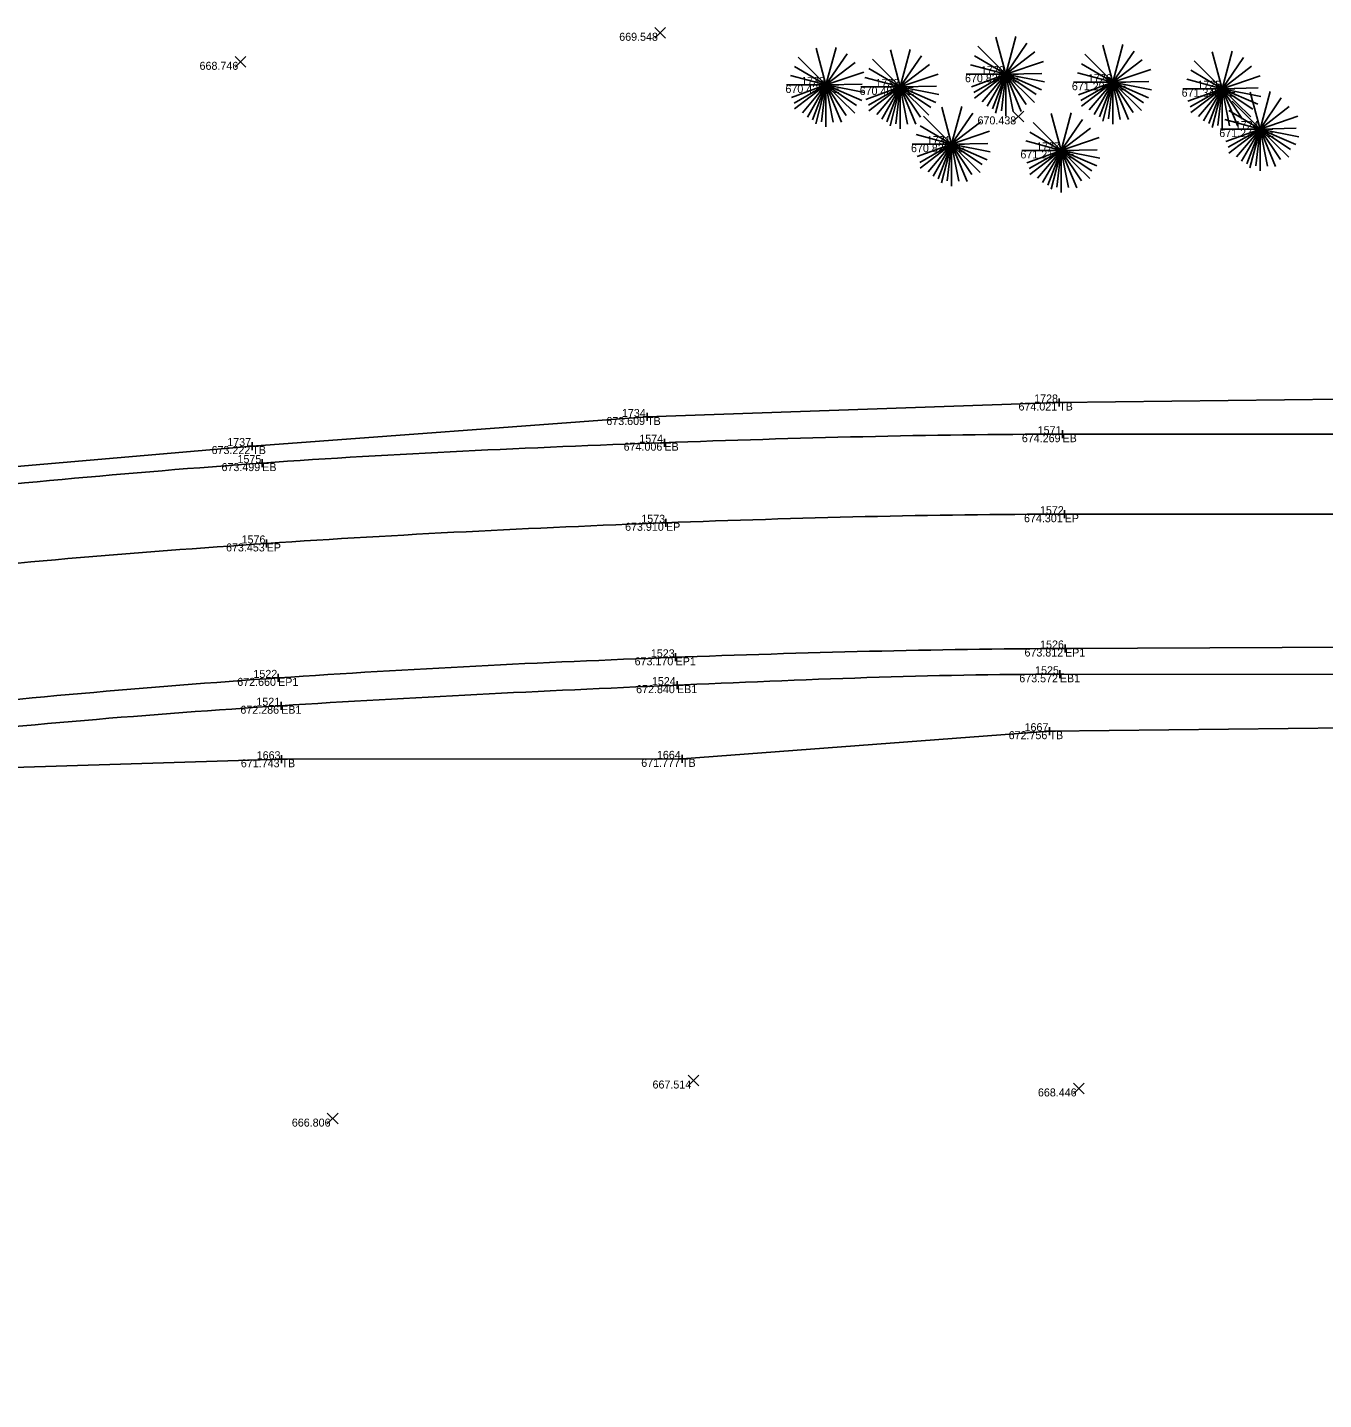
# Model space of a CAD drawing. Extents: x 2197382 to 2204062, y 634117 to 636522.
# Drawn here: x 2203379.7 to 2203541.7, y 635413 to 635584.5 of the extents above; entities that cross this region are included whole.
import ezdxf

# ---------------------------------------------------------------- set-up
doc = ezdxf.new("R2010")
doc.units = 0
for name, color, linetype in [('_CIVIL_CONSTRUCTION', 7, 'Continuous'), ('GE_P_Alignment_100_Bearings', 7, 'Continuous'), ('GE_P_Alignment_100_Distances', 7, 'Continuous'), ('GE_X_Alignment', 7, 'Continuous'), ('PF_P_Grade_Line', 7, 'Continuous'), ('RW_X_CL_100_Curve_Data', 7, 'Continuous'), ('SH_Border', 7, 'Continuous'), ('SH_Cut_Line', 7, 'Continuous'), ('SH_Data', 7, 'Continuous')]:
    doc.layers.add(name, color=color, linetype=linetype)

msp = doc.modelspace()

# ---------------------------------------------------------------- linework, layer by layer
at = {"layer": '_CIVIL_CONSTRUCTION'}
for p, q in [((2203508.13, 635537.6), (2203509.13, 635537.6)), ((2203508.63, 635538.1), (2203508.63, 635537.1)), ((2203508.63, 635537.6), (2203508.63, 635537.6)), ((2203456.64, 635535.79), (2203457.64, 635535.79)), ((2203457.14, 635536.29), (2203457.14, 635535.29)), ((2203457.14, 635535.79), (2203457.14, 635535.79)), ((2203508.55, 635533.64), (2203509.55, 635533.64)), ((2203509.05, 635534.14), (2203509.05, 635533.14)), ((2203509.05, 635533.64), (2203509.05, 635533.64)), ((2203407.3, 635532.16), (2203408.3, 635532.16)), ((2203407.8, 635532.66), (2203407.8, 635531.66)), ((2203407.8, 635532.16), (2203407.8, 635532.16)), ((2203458.81, 635532.58), (2203459.81, 635532.58)), ((2203459.31, 635533.08), (2203459.31, 635532.08)), ((2203459.31, 635532.58), (2203459.31, 635532.58)), ((2203408.55, 635530.03), (2203409.55, 635530.03)), ((2203409.05, 635530.53), (2203409.05, 635529.53)), ((2203409.05, 635530.03), (2203409.05, 635530.03)), ((2203459.5, 635523.07), (2203459.5, 635522.07)), ((2203508.82, 635523.64), (2203509.82, 635523.64)), ((2203509.32, 635524.14), (2203509.32, 635523.14)), ((2203509.32, 635523.64), (2203509.32, 635523.64)), ((2203459, 635522.57), (2203460, 635522.57)), ((2203459.5, 635522.57), (2203459.5, 635522.57)), ((2203409.1, 635519.99), (2203410.1, 635519.99)), ((2203409.6, 635520.49), (2203409.6, 635519.49)), ((2203409.6, 635519.99), (2203409.6, 635519.99)), ((2203460.7, 635506.26), (2203460.7, 635505.26)), ((2203508.87, 635506.86), (2203509.87, 635506.86)), ((2203509.37, 635507.36), (2203509.37, 635506.36)), ((2203509.37, 635506.86), (2203509.37, 635506.86)), ((2203460.2, 635505.76), (2203461.2, 635505.76)), ((2203460.7, 635505.76), (2203460.7, 635505.76)), ((2203508.72, 635504.14), (2203508.72, 635503.14)), ((2203410.54, 635503.19), (2203411.54, 635503.19)), ((2203411.04, 635503.69), (2203411.04, 635502.69)), ((2203411.04, 635503.19), (2203411.04, 635503.19)), ((2203460.88, 635502.78), (2203460.88, 635501.78)), ((2203508.22, 635503.64), (2203509.22, 635503.64)), ((2203508.72, 635503.64), (2203508.72, 635503.64)), ((2203460.38, 635502.28), (2203461.38, 635502.28)), ((2203460.88, 635502.28), (2203460.88, 635502.28)), ((2203410.92, 635499.71), (2203411.92, 635499.71)), ((2203411.42, 635500.21), (2203411.42, 635499.21)), ((2203411.42, 635499.71), (2203411.42, 635499.71)), ((2203506.92, 635496.53), (2203507.92, 635496.53)), ((2203507.42, 635497.03), (2203507.42, 635496.03)), ((2203507.42, 635496.53), (2203507.42, 635496.53)), ((2203410.95, 635493.02), (2203411.95, 635493.02)), ((2203411.45, 635493.52), (2203411.45, 635492.52)), ((2203411.45, 635493.02), (2203411.45, 635493.02)), ((2203461.01, 635493.07), (2203462.01, 635493.07)), ((2203461.51, 635493.57), (2203461.51, 635492.57)), ((2203461.51, 635493.07), (2203461.51, 635493.07))]:
    msp.add_line(p, q, dxfattribs=at)
at = {"layer": 'GE_P_Alignment_100_Bearings'}
for p, q in [((2203501.95, 635578.62), (2203500.72, 635583.23)), ((2203501.95, 635578.62), (2203503.21, 635583.32)), ((2203479.49, 635577.28), (2203478.25, 635581.89)), ((2203479.49, 635577.28), (2203480.75, 635581.97)), ((2203488.78, 635577.03), (2203487.54, 635581.65)), ((2203488.78, 635577.03), (2203490.03, 635581.73)), ((2203501.95, 635578.62), (2203498.46, 635582.11)), ((2203501.95, 635578.62), (2203504.61, 635582.51)), ((2203501.95, 635578.62), (2203505.61, 635581.43)), ((2203515.34, 635577.62), (2203514.11, 635582.23)), ((2203515.34, 635577.62), (2203516.6, 635582.32)), ((2203515.34, 635577.62), (2203518, 635581.51)), ((2203529, 635576.81), (2203527.77, 635581.42)), ((2203529, 635576.81), (2203530.26, 635581.51)), ((2203479.49, 635577.28), (2203475.58, 635579.57)), ((2203479.49, 635577.28), (2203476, 635580.76)), ((2203479.49, 635577.28), (2203482.15, 635581.16)), ((2203479.49, 635577.28), (2203483.15, 635580.08)), ((2203488.78, 635577.03), (2203485.29, 635580.52)), ((2203488.78, 635577.03), (2203491.43, 635580.92)), ((2203488.78, 635577.03), (2203492.43, 635579.84)), ((2203501.95, 635578.62), (2203497.54, 635579.8)), ((2203501.95, 635578.62), (2203498.05, 635580.92)), ((2203501.95, 635578.62), (2203506.69, 635580.23)), ((2203515.34, 635577.62), (2203511.44, 635579.92)), ((2203515.34, 635577.62), (2203511.85, 635581.11)), ((2203515.34, 635577.62), (2203519, 635580.42)), ((2203529, 635576.81), (2203525.51, 635580.3)), ((2203529, 635576.81), (2203531.66, 635580.7)), ((2203529, 635576.81), (2203532.66, 635579.62)), ((2203479.49, 635577.28), (2203475.08, 635578.46)), ((2203479.49, 635577.28), (2203484.23, 635578.88)), ((2203488.78, 635577.03), (2203484.36, 635578.22)), ((2203488.78, 635577.03), (2203484.87, 635579.33)), ((2203488.78, 635577.03), (2203493.51, 635578.64)), ((2203497.02, 635578.62), (2203501.95, 635578.62)), ((2203501.95, 635578.62), (2203497.66, 635577.06)), ((2203501.95, 635578.62), (2203497.97, 635576.34)), ((2203501.95, 635578.62), (2203498.05, 635575.63)), ((2203501.95, 635578.62), (2203499.01, 635575.15)), ((2203501.95, 635578.62), (2203499.63, 635574.61)), ((2203501.95, 635578.62), (2203500.29, 635574.28)), ((2203501.95, 635578.62), (2203500.69, 635573.76)), ((2203501.95, 635578.62), (2203501.41, 635574.03)), ((2203501.95, 635578.62), (2203506.46, 635578.71)), ((2203501.95, 635573.38), (2203501.95, 635578.62)), ((2203501.95, 635578.62), (2203502.87, 635573.98)), ((2203501.95, 635578.62), (2203503.89, 635573.95)), ((2203501.95, 635578.62), (2203504.49, 635574.83)), ((2203501.95, 635578.62), (2203505.54, 635575.1)), ((2203501.95, 635578.62), (2203505.77, 635576.07)), ((2203501.95, 635578.62), (2203506.42, 635576.68)), ((2203501.95, 635578.62), (2203506.78, 635577.66)), ((2203515.34, 635577.62), (2203510.93, 635578.8)), ((2203515.34, 635577.62), (2203520.08, 635579.23)), ((2203529, 635576.81), (2203524.59, 635577.99)), ((2203529, 635576.81), (2203525.1, 635579.11)), ((2203529, 635576.81), (2203533.74, 635578.42)), ((2203474.55, 635577.28), (2203479.49, 635577.28)), ((2203479.49, 635577.28), (2203475.2, 635575.71)), ((2203479.49, 635577.28), (2203475.51, 635574.99)), ((2203479.49, 635577.28), (2203475.58, 635574.28)), ((2203479.49, 635577.28), (2203476.54, 635573.81)), ((2203479.49, 635577.28), (2203477.17, 635573.26)), ((2203479.49, 635577.28), (2203477.82, 635572.94)), ((2203479.49, 635577.28), (2203478.23, 635572.42)), ((2203479.49, 635577.28), (2203478.95, 635572.68)), ((2203479.49, 635577.28), (2203484, 635577.37)), ((2203479.49, 635572.04), (2203479.49, 635577.28)), ((2203479.49, 635577.28), (2203480.41, 635572.64)), ((2203479.49, 635577.28), (2203481.42, 635572.61)), ((2203479.49, 635577.28), (2203482.03, 635573.48)), ((2203479.49, 635577.28), (2203483.08, 635573.75)), ((2203479.49, 635577.28), (2203483.31, 635574.72)), ((2203479.49, 635577.28), (2203483.96, 635575.33)), ((2203479.49, 635577.28), (2203484.32, 635576.32)), ((2203483.84, 635577.03), (2203488.78, 635577.03)), ((2203488.78, 635577.03), (2203484.49, 635575.47)), ((2203488.78, 635577.03), (2203484.79, 635574.75)), ((2203488.78, 635577.03), (2203484.87, 635574.04)), ((2203488.78, 635577.03), (2203485.83, 635573.57)), ((2203488.78, 635577.03), (2203486.46, 635573.02)), ((2203488.78, 635577.03), (2203487.11, 635572.69)), ((2203488.78, 635577.03), (2203487.51, 635572.18)), ((2203488.78, 635577.03), (2203488.23, 635572.44)), ((2203488.78, 635577.03), (2203493.29, 635577.12)), ((2203488.78, 635571.79), (2203488.78, 635577.03)), ((2203488.78, 635577.03), (2203489.7, 635572.4)), ((2203488.78, 635577.03), (2203490.71, 635572.36)), ((2203488.78, 635577.03), (2203491.31, 635573.24)), ((2203488.78, 635577.03), (2203492.36, 635573.51)), ((2203488.78, 635577.03), (2203492.6, 635574.48)), ((2203488.78, 635577.03), (2203493.24, 635575.09)), ((2203488.78, 635577.03), (2203493.6, 635576.07)), ((2203510.41, 635577.62), (2203515.34, 635577.62)), ((2203515.34, 635577.62), (2203511.05, 635576.06)), ((2203515.34, 635577.62), (2203511.36, 635575.34)), ((2203515.34, 635577.62), (2203511.44, 635574.62)), ((2203515.34, 635577.62), (2203512.4, 635574.15)), ((2203515.34, 635577.62), (2203513.02, 635573.6)), ((2203515.34, 635577.62), (2203513.68, 635573.28)), ((2203515.34, 635577.62), (2203514.08, 635572.76)), ((2203515.34, 635577.62), (2203514.8, 635573.03)), ((2203515.34, 635577.62), (2203519.85, 635577.71)), ((2203515.34, 635572.38), (2203515.34, 635577.62)), ((2203515.34, 635577.62), (2203516.26, 635572.98)), ((2203515.34, 635577.62), (2203517.28, 635572.95)), ((2203515.34, 635577.62), (2203517.88, 635573.83)), ((2203515.34, 635577.62), (2203518.93, 635574.1)), ((2203515.34, 635577.62), (2203519.16, 635575.06)), ((2203515.34, 635577.62), (2203519.81, 635575.68)), ((2203515.34, 635577.62), (2203520.17, 635576.66)), ((2203524.07, 635576.81), (2203529, 635576.81)), ((2203529, 635576.81), (2203524.71, 635575.25)), ((2203529, 635576.81), (2203525.02, 635574.53)), ((2203529, 635576.81), (2203525.1, 635573.82)), ((2203529, 635576.81), (2203526.06, 635573.34)), ((2203529, 635576.81), (2203526.68, 635572.8)), ((2203529, 635576.81), (2203527.34, 635572.47)), ((2203529, 635576.81), (2203527.74, 635571.95)), ((2203529, 635576.81), (2203528.46, 635572.22)), ((2203529, 635576.81), (2203533.51, 635576.9)), ((2203529, 635571.57), (2203529, 635576.81)), ((2203529, 635576.81), (2203529.92, 635572.17)), ((2203529, 635576.81), (2203530.94, 635572.14)), ((2203529, 635576.81), (2203531.54, 635573.02)), ((2203529, 635576.81), (2203532.59, 635573.29)), ((2203529, 635576.81), (2203532.82, 635574.26)), ((2203529, 635576.81), (2203533.47, 635574.87)), ((2203529, 635576.81), (2203533.83, 635575.85)), ((2203533.73, 635571.77), (2203532.5, 635576.38)), ((2203533.73, 635571.77), (2203534.99, 635576.47)), ((2203495.19, 635569.88), (2203493.96, 635574.5)), ((2203495.19, 635569.88), (2203496.45, 635574.58)), ((2203533.73, 635571.77), (2203530.25, 635575.26)), ((2203533.73, 635571.77), (2203536.39, 635575.65)), ((2203533.73, 635571.77), (2203537.39, 635574.57)), ((2203495.19, 635569.88), (2203491.7, 635573.37)), ((2203495.19, 635569.88), (2203497.84, 635573.77)), ((2203508.88, 635569.1), (2203507.65, 635573.71)), ((2203508.88, 635569.1), (2203510.14, 635573.8)), ((2203508.88, 635569.1), (2203511.54, 635572.98)), ((2203533.73, 635571.77), (2203529.32, 635572.95)), ((2203533.73, 635571.77), (2203529.83, 635574.07)), ((2203533.73, 635571.77), (2203538.47, 635573.38)), ((2203495.19, 635569.88), (2203490.78, 635571.07)), ((2203495.19, 635569.88), (2203491.28, 635572.18)), ((2203495.19, 635569.88), (2203498.85, 635572.69)), ((2203495.19, 635569.88), (2203499.93, 635571.49)), ((2203508.88, 635569.1), (2203504.98, 635571.39)), ((2203508.88, 635569.1), (2203505.39, 635572.58)), ((2203508.88, 635569.1), (2203512.54, 635571.9)), ((2203528.8, 635571.77), (2203533.73, 635571.77)), ((2203533.73, 635571.77), (2203529.44, 635570.21)), ((2203533.73, 635571.77), (2203529.75, 635569.49)), ((2203533.73, 635571.77), (2203529.83, 635568.77)), ((2203533.73, 635571.77), (2203530.79, 635568.3)), ((2203533.73, 635571.77), (2203531.42, 635567.75)), ((2203533.73, 635571.77), (2203532.07, 635567.43)), ((2203533.73, 635571.77), (2203532.47, 635566.91)), ((2203533.73, 635571.77), (2203533.19, 635567.18)), ((2203533.73, 635571.77), (2203538.25, 635571.86)), ((2203533.73, 635566.53), (2203533.73, 635571.77)), ((2203533.73, 635571.77), (2203534.66, 635567.13)), ((2203533.73, 635571.77), (2203535.67, 635567.1)), ((2203533.73, 635571.77), (2203536.27, 635567.98)), ((2203533.73, 635571.77), (2203537.32, 635568.25)), ((2203533.73, 635571.77), (2203537.56, 635569.21)), ((2203533.73, 635571.77), (2203538.2, 635569.83)), ((2203533.73, 635571.77), (2203538.56, 635570.81)), ((2203490.25, 635569.88), (2203495.19, 635569.88)), ((2203495.19, 635569.88), (2203490.9, 635568.32)), ((2203495.19, 635569.88), (2203491.21, 635567.6)), ((2203495.19, 635569.88), (2203491.28, 635566.89)), ((2203495.19, 635569.88), (2203492.25, 635566.42)), ((2203495.19, 635569.88), (2203492.87, 635565.87)), ((2203495.19, 635569.88), (2203493.52, 635565.54)), ((2203495.19, 635569.88), (2203493.93, 635565.03)), ((2203495.19, 635569.88), (2203494.65, 635565.29)), ((2203495.19, 635569.88), (2203499.7, 635569.98)), ((2203495.19, 635564.64), (2203495.19, 635569.88)), ((2203495.19, 635569.88), (2203496.11, 635565.25)), ((2203495.19, 635569.88), (2203497.12, 635565.22)), ((2203495.19, 635569.88), (2203497.73, 635566.09)), ((2203495.19, 635569.88), (2203498.78, 635566.36)), ((2203495.19, 635569.88), (2203499.01, 635567.33)), ((2203495.19, 635569.88), (2203499.65, 635567.94)), ((2203495.19, 635569.88), (2203500.02, 635568.93)), ((2203508.88, 635569.1), (2203504.47, 635570.28)), ((2203508.88, 635569.1), (2203513.62, 635570.7)), ((2203503.95, 635569.1), (2203508.88, 635569.1)), ((2203508.88, 635569.1), (2203504.59, 635567.54)), ((2203508.88, 635569.1), (2203504.9, 635566.82)), ((2203508.88, 635569.1), (2203504.98, 635566.1)), ((2203508.88, 635569.1), (2203505.94, 635565.63)), ((2203508.88, 635569.1), (2203506.56, 635565.08)), ((2203508.88, 635569.1), (2203507.22, 635564.76)), ((2203508.88, 635569.1), (2203507.62, 635564.24)), ((2203508.88, 635569.1), (2203508.34, 635564.51)), ((2203508.88, 635569.1), (2203513.39, 635569.19)), ((2203508.88, 635563.86), (2203508.88, 635569.1)), ((2203508.88, 635569.1), (2203509.8, 635564.46)), ((2203508.88, 635569.1), (2203510.82, 635564.43)), ((2203508.88, 635569.1), (2203511.42, 635565.3)), ((2203508.88, 635569.1), (2203512.47, 635565.58)), ((2203508.88, 635569.1), (2203512.7, 635566.54)), ((2203508.88, 635569.1), (2203513.35, 635567.16)), ((2203508.88, 635569.1), (2203513.71, 635568.14))]:
    msp.add_line(p, q, dxfattribs=at)
at = {"layer": 'GE_P_Alignment_100_Distances'}
for p, q in [((2203559.07, 635523.65), (2203509.32, 635523.64)), ((2203509.37, 635506.86), (2203559.68, 635507.08))]:
    msp.add_line(p, q, dxfattribs=at)
for points in [[(2203509.32, 635523.64), (2203492.71, 635523.63), (2203459.45, 635522.77), (2203409.62, 635520.27), (2203359.91, 635516.08), (2203310.49, 635509.4), (2203261.11, 635501.99), (2203212.05, 635492.43), (2203163.49, 635480.65), (2203115.29, 635467.72), (2203067.64, 635452.84), (2203020.4, 635437.15), (2202989.52, 635425.13), (2202974.27, 635418.84)], [(2203026.75, 635422.16), (2203041.87, 635427.74), (2203072.98, 635437.38), (2203119.81, 635452.49), (2203167.64, 635464.69), (2203215.6, 635476.19), (2203263.86, 635485.77), (2203312.69, 635493.22), (2203361.79, 635499.12), (2203411.11, 635503.52), (2203460.35, 635505.94), (2203493.14, 635506.79), (2203509.37, 635506.86)]]:
    msp.add_open_spline(points, degree=3, dxfattribs=at)
at = {"layer": 'GE_X_Alignment'}
for p, q in [((2203559.57, 635533.65), (2203509.05, 635533.64)), ((2203508.72, 635503.64), (2203559.76, 635503.6))]:
    msp.add_line(p, q, dxfattribs=at)
for points in [[(2203509.05, 635533.64), (2203492.46, 635533.63), (2203459.12, 635532.73), (2203409.1, 635530.45), (2203358.98, 635525.69), (2203309.16, 635519.46), (2203259.64, 635511.38), (2203210.26, 635501.87), (2203160.94, 635490.69), (2203112.43, 635476.96), (2203063.47, 635464.85), (2203018.46, 635445.24), (2202987.96, 635434.05), (2202973.99, 635427.15)], [(2203012.65, 635413.01), (2203017.91, 635415.43), (2203039, 635420.9), (2203074.31, 635435.09), (2203121.35, 635447.89), (2203168.65, 635461.38), (2203216.37, 635472.84), (2203264.58, 635481.88), (2203313.28, 635489.5), (2203362.17, 635495.91), (2203411.48, 635500.02), (2203460.32, 635502.3), (2203492.76, 635503.65), (2203508.72, 635503.64)]]:
    msp.add_open_spline(points, degree=3, dxfattribs=at)
at = {"layer": 'PF_P_Grade_Line'}
for points in [[(2203905.24, 635544.12), (2203857.35, 635543.05), (2203808.12, 635540.24), (2203758.65, 635537.75), (2203707.87, 635536.99), (2203658.67, 635537.69), (2203608.57, 635538.61), (2203557.91, 635538.19), (2203508.63, 635537.6), (2203457.14, 635535.79), (2203407.8, 635532.16), (2203358.09, 635527.85), (2203307.62, 635521.36), (2203257.61, 635512.38), (2203209.52, 635502.64), (2203160.69, 635490.38), (2203110.74, 635480.72), (2203062.69, 635468.06), (2203015.53, 635449.98), (2202971.3, 635427.61)], [(2203043.47, 635419.84), (2203073.57, 635429.53), (2203121.13, 635443.22), (2203169.12, 635455.8), (2203217.36, 635467.56), (2203230.84, 635471.04), (2203265.33, 635478.99), (2203314.75, 635483.37), (2203364.47, 635491.57), (2203411.45, 635493.02), (2203461.51, 635493.07), (2203507.42, 635496.53), (2203559.6, 635497.11), (2203609.33, 635499.7), (2203659.06, 635500.52), (2203709.25, 635500.73), (2203757.56, 635500.46), (2203810.24, 635498.93), (2203858.69, 635500.09), (2203907.88, 635499.67), (2203958.73, 635497.99), (2204007.22, 635491.87), (2204054.41, 635491.83)]]:
    msp.add_lwpolyline(points, dxfattribs=at)
at = {"layer": 'RW_X_CL_100_Curve_Data'}
for p, q in [((2203458.1, 635583.13), (2203459.43, 635584.47)), ((2203458.1, 635584.47), (2203459.43, 635583.13)), ((2203405.66, 635579.5), (2203406.99, 635580.84)), ((2203405.66, 635580.84), (2203406.99, 635579.5)), ((2203502.86, 635572.68), (2203504.2, 635574.01)), ((2203502.86, 635574.01), (2203504.2, 635572.68)), ((2203462.28, 635452.21), (2203463.61, 635453.55)), ((2203462.28, 635453.55), (2203463.61, 635452.21)), ((2203510.41, 635451.22), (2203511.75, 635452.56)), ((2203510.41, 635452.56), (2203511.75, 635451.22)), ((2203417.18, 635447.46), (2203418.52, 635448.79)), ((2203417.18, 635448.79), (2203418.52, 635447.46))]:
    msp.add_line(p, q, dxfattribs=at)

# ---------------------------------------------------------------- texts
at = {"layer": 'SH_Border'}
for s, p in [('TE', (2203501.95, 635577.62)), ('TE', (2203479.49, 635576.28)), ('TE', (2203488.78, 635576.03)), ('TE', (2203515.34, 635576.62)), ('TE', (2203529, 635575.81)), ('TE', (2203533.73, 635570.77)), ('TE', (2203495.19, 635568.88)), ('TE', (2203508.88, 635568.1)), ('TB', (2203508.63, 635536.6)), ('TB', (2203457.14, 635534.79)), ('EB', (2203509.05, 635532.64)), ('TB', (2203407.8, 635531.16)), ('EB', (2203459.31, 635531.58)), ('EB', (2203409.05, 635529.03)), ('EP', (2203509.32, 635522.64)), ('EP', (2203459.5, 635521.57)), ('EP', (2203409.6, 635518.99)), ('EP1', (2203509.37, 635505.86)), ('EP1', (2203460.7, 635504.76)), ('EP1', (2203411.04, 635502.19)), ('EB1', (2203508.72, 635502.64)), ('EB1', (2203460.88, 635501.28)), ('EB1', (2203411.42, 635498.71)), ('TB', (2203507.42, 635495.53)), ('TB', (2203411.45, 635492.02)), ('TB', (2203461.51, 635492.07))]:
    msp.add_text(s, height=1, dxfattribs=at).set_placement(p)
at = {"layer": 'SH_Cut_Line'}
for s, p in [('1729', (2203498.85, 635578.62)), ('1733', (2203476.41, 635577.28)), ('1732', (2203485.68, 635577.03)), ('1726', (2203512.22, 635577.62)), ('1725', (2203525.91, 635576.81)), ('1724', (2203530.59, 635571.77)), ('1731', (2203492.09, 635569.88)), ('1727', (2203505.77, 635569.1)), ('1728', (2203505.51, 635537.6)), ('1734', (2203454, 635535.79)), ('1574', (2203456.17, 635532.58)), ('1571', (2203505.95, 635533.64)), ('1737', (2203404.68, 635532.16)), ('1575', (2203405.96, 635530.03)), ('1573', (2203456.42, 635522.57)), ('1572', (2203506.23, 635523.64)), ('1576', (2203406.47, 635519.99)), ('1526', (2203506.25, 635506.86)), ('1523', (2203457.61, 635505.76)), ('1522', (2203407.95, 635503.19)), ('1525', (2203505.63, 635503.64)), ('1524', (2203457.74, 635502.28)), ('1521', (2203408.32, 635499.71)), ('1667', (2203504.31, 635496.53)), ('1663', (2203408.36, 635493.02)), ('1664', (2203458.37, 635493.07))]:
    msp.add_text(s, height=1, dxfattribs=at).set_placement(p)
at = {"layer": 'SH_Data'}
for s, p in [('669.548', (2203453.66, 635582.8)), ('668.746', (2203401.22, 635579.17)), ('670.829', (2203496.87, 635577.62)), ('670.433', (2203474.43, 635576.28)), ('670.402', (2203483.7, 635576.03)), ('671.294', (2203510.22, 635576.62)), ('671.343', (2203523.94, 635575.81)), ('670.438', (2203498.43, 635572.35)), ('671.277', (2203528.64, 635570.77)), ('670.822', (2203490.12, 635568.88)), ('671.217', (2203503.79, 635568.1)), ('674.021', (2203503.55, 635536.6)), ('673.609', (2203452.05, 635534.79)), ('674.269', (2203503.97, 635532.64)), ('673.222', (2203402.72, 635531.16)), ('674.006', (2203454.21, 635531.58)), ('673.499', (2203403.96, 635529.03)), ('674.301', (2203504.24, 635522.64)), ('673.910', (2203454.39, 635521.57)), ('673.453', (2203404.53, 635518.99)), ('673.812', (2203504.3, 635505.86)), ('673.170', (2203455.58, 635504.76)), ('672.660', (2203405.93, 635502.19)), ('673.572', (2203503.65, 635502.64)), ('672.840', (2203455.77, 635501.28)), ('672.286', (2203406.32, 635498.71)), ('672.756', (2203502.32, 635495.53)), ('671.743', (2203406.38, 635492.02)), ('671.777', (2203456.41, 635492.07)), ('667.514', (2203457.82, 635451.88)), ('668.446', (2203505.98, 635450.89)), ('666.806', (2203412.75, 635447.12))]:
    msp.add_text(s, height=1, dxfattribs=at).set_placement(p)

doc.saveas('drawing.dxf')
